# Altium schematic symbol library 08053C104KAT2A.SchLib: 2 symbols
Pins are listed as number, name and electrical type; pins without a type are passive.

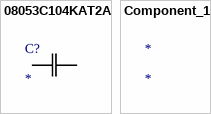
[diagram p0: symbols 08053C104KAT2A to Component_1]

## 08053C104KAT2A
designator C?
No Description Available; Mfr_Name: KYOCERA AVX
footprint CAP_X7R_0805_AVX
pins: 1, 2

## Component_1
designator *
